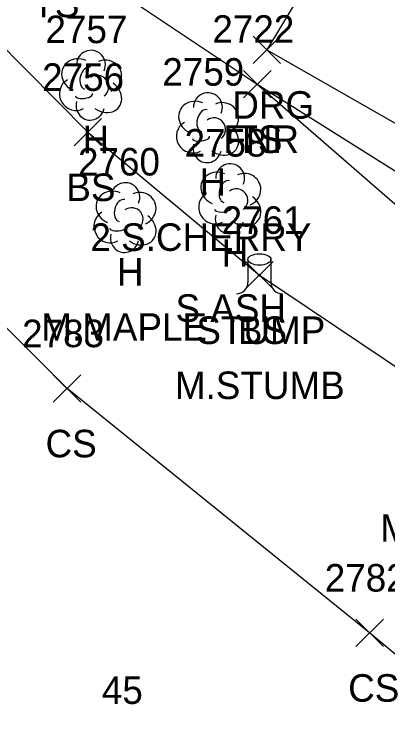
# Model space of a CAD drawing. Extents: x 1499292 to 1501024, y 534584 to 538043.
# Drawn here: x 1499593.1 to 1499620.2, y 537765.7 to 537816.8 of the extents above; entities that cross this region are included whole.
import ezdxf

# ---------------------------------------------------------------- set-up
doc = ezdxf.new("R2010")
doc.units = 0
for name, color, linetype in [('C_I', 7, 'Continuous'), ('L_A', 7, 'Continuous'), ('L_C', 7, 'Continuous'), ('L_I', 7, 'Continuous'), ('L_TIC', 7, 'Continuous'), ('LELB', 7, 'Continuous'), ('LFNC', 7, 'Continuous'), ('LTD', 7, 'Continuous'), ('LTS', 7, 'Continuous'), ('R_A', 7, 'Continuous'), ('R_TIC', 7, 'Continuous'), ('RDG', 7, 'Continuous')]:
    doc.layers.add(name, color=color, linetype=linetype)

msp = doc.modelspace()

# ---------------------------------------------------------------- linework, layer by layer
at = {"layer": 'L_TIC'}
for points in [[(1499609.739, 537810.692), (1499611.739, 537812.692)], [(1499611.739, 537810.692), (1499609.739, 537812.692)], [(1499609.739, 537810.692), (1499611.739, 537812.692)], [(1499611.739, 537810.692), (1499609.739, 537812.692)], [(1499597.435, 537807.198), (1499599.435, 537809.198)], [(1499599.435, 537807.198), (1499597.435, 537809.198)], [(1499609.893, 537796.818), (1499611.893, 537798.818)], [(1499611.893, 537796.818), (1499609.893, 537798.818)], [(1499595.925, 537788.586), (1499597.925, 537790.586)], [(1499597.925, 537788.586), (1499595.925, 537790.586)], [(1499617.899, 537770.836), (1499619.899, 537772.836)], [(1499619.899, 537770.836), (1499617.899, 537772.836)]]:
    msp.add_lwpolyline(points, dxfattribs=at)
at = {"layer": 'LELB'}
for points in [[(1499309.186, 537981.429), (1499342.601, 537967.946), (1499383.002, 537948.454), (1499403.335, 537937.322), (1499425.862, 537923.972), (1499462.056, 537903.885), (1499477.958, 537896.437), (1499498.482, 537885.281), (1499524.089, 537871.298), (1499544.155, 537861.141), (1499587.091, 537836.791), (1499598.177, 537827.35), (1499596, 537821.552), (1499610.739, 537811.692), (1499624.068, 537800.087), (1499630.641, 537795.692), (1499636.949, 537791.6), (1499648.607, 537781.35)], [(1499473.284, 537889.721), (1499498.471, 537879.808), (1499498.645, 537874.964), (1499522.472, 537856.451), (1499547.406, 537847.481), (1499543.068, 537839.362), (1499550.539, 537830.456), (1499554.894, 537825.457), (1499558.691, 537827.698), (1499558.309, 537830.261), (1499565.321, 537832.423), (1499575.95, 537829.995), (1499584.046, 537827.015), (1499587.206, 537819.565), (1499598.435, 537808.198), (1499610.893, 537797.818), (1499632.622, 537783.246), (1499641.436, 537777.369), (1499648.073, 537774.807), (1499656.022, 537768.512), (1499664.288, 537756.487)], [(1499660.39, 537740.632), (1499639.629, 537754.597), (1499618.899, 537771.836), (1499596.925, 537789.586), (1499575.999, 537810.483), (1499560.292, 537815.474)]]:
    msp.add_lwpolyline(points, dxfattribs=at)
at = {"layer": 'LFNC'}
msp.add_lwpolyline([(1499610.739, 537811.692), (1499626.25, 537801.938), (1499645.323, 537790.222), (1499651.803, 537781.891)], dxfattribs=at)
at = {"layer": 'LTD'}
for p, q in [((1499598.619, 537811.668), (1499598.619, 537811.668)), ((1499598.619, 537811.668), (1499598.619, 537811.668)), ((1499607.113, 537808.578), (1499607.113, 537808.578)), ((1499607.113, 537808.578), (1499607.113, 537808.578)), ((1499608.725, 537803.426), (1499608.725, 537803.426)), ((1499608.725, 537803.426), (1499608.725, 537803.426)), ((1499601.118, 537802.053), (1499601.118, 537802.053)), ((1499601.118, 537802.053), (1499601.118, 537802.053))]:
    msp.add_line(p, q, dxfattribs=at)
for centre in [(1499598.666, 537813.102), (1499607.159, 537810.012), (1499608.772, 537804.86), (1499601.164, 537803.487)]:
    msp.add_arc(centre, 1.047, 335.5272, 180.9563, dxfattribs=at)
for centre, major_axis, ratio, start_param, end_param in [((1499597.828, 537812.334), (1.21, -0.512), 0.895232, 1.570796, 4.712389), ((1499599.661, 537812.251), (-1.141, -0.483), 0.949671, 1.570796, 4.712389), ((1499598.411, 537812.126), (-0.208, -0.792), 0.645439, 3.141593, 6.283185), ((1499599.119, 537811.501), (-0.5, 0.667), 0.989748, 3.141593, 6.283185), ((1499597.536, 537810.959), (0.584, -1.042), 0.959034, 3.141593, 6.283185), ((1499599.62, 537810.835), (-1.09, 0.792), 0.841452, 1.570796, 4.712389), ((1499598.161, 537810.918), (-0.625, -0.083), 0.423636, 0, 3.141593), ((1499598.62, 537810.168), (0.265, 1.061), 0.942809, 1.570796, 4.712389), ((1499606.321, 537809.245), (1.21, -0.512), 0.895232, 1.570796, 4.712389), ((1499608.154, 537809.162), (-1.141, -0.483), 0.949671, 1.570796, 4.712389), ((1499606.904, 537809.037), (-0.208, -0.792), 0.645439, 3.141593, 6.283185), ((1499607.613, 537808.412), (-0.5, 0.667), 0.989748, 3.141593, 6.283185), ((1499606.029, 537807.87), (0.584, -1.042), 0.959034, 3.141593, 6.283185), ((1499608.113, 537807.745), (-1.09, 0.792), 0.841452, 1.570796, 4.712389), ((1499606.654, 537807.828), (-0.625, -0.083), 0.423636, 0, 3.141593), ((1499607.113, 537807.078), (0.265, 1.061), 0.942809, 1.570796, 4.712389), ((1499607.933, 537804.093), (1.21, -0.512), 0.895232, 1.570796, 4.712389), ((1499609.767, 537804.01), (-1.141, -0.483), 0.949671, 1.570796, 4.712389), ((1499608.517, 537803.884), (-0.208, -0.792), 0.645439, 3.141593, 6.283185), ((1499600.326, 537802.719), (1.21, -0.512), 0.895232, 1.570796, 4.712389), ((1499609.225, 537803.26), (-0.5, 0.667), 0.989748, 3.141593, 6.283185), ((1499602.159, 537802.636), (-1.141, -0.483), 0.949671, 1.570796, 4.712389), ((1499607.642, 537802.718), (0.584, -1.042), 0.959034, 3.141593, 6.283185), ((1499600.909, 537802.511), (-0.208, -0.792), 0.645439, 3.141593, 6.283185), ((1499609.725, 537802.593), (-1.09, 0.792), 0.841452, 1.570796, 4.712389), ((1499601.618, 537801.886), (-0.5, 0.667), 0.989748, 3.141593, 6.283185), ((1499608.267, 537802.676), (-0.625, -0.083), 0.423636, 0, 3.141593), ((1499600.034, 537801.344), (0.584, -1.042), 0.959034, 3.141593, 6.283185), ((1499602.118, 537801.22), (-1.09, 0.792), 0.841452, 1.570796, 4.712389), ((1499608.725, 537801.926), (0.265, 1.061), 0.942809, 1.570796, 4.712389), ((1499600.659, 537801.303), (-0.625, -0.083), 0.423636, 0, 3.141593), ((1499601.118, 537800.553), (0.265, 1.061), 0.942809, 1.570796, 4.712389)]:
    msp.add_ellipse(centre, major_axis=major_axis, ratio=ratio, start_param=start_param, end_param=end_param, dxfattribs=at)
at = {"layer": 'LTS'}
for p, q in [((1499610.064, 537798.958), (1499610.064, 537797.291)), ((1499611.73, 537798.791), (1499611.73, 537798.958)), ((1499611.73, 537798.958), (1499611.73, 537797.291)), ((1499610.897, 537797.815), (1499610.897, 537797.815)), ((1499610.897, 537797.815), (1499610.897, 537797.815)), ((1499610.897, 537797.791), (1499610.897, 537797.791))]:
    msp.add_line(p, q, dxfattribs=at)
msp.add_circle((1499610.897, 537797.815), 0.0833, dxfattribs=at)
for centre, start, end in [((1499609.23, 537797.291), 270, 360), ((1499612.564, 537797.291), 180, 270)]:
    msp.add_arc(centre, 0.833, start, end, dxfattribs=at)
msp.add_ellipse((1499610.897, 537798.958), major_axis=(-0.833, 0), ratio=0.5, dxfattribs=at)
at = {"layer": 'R_TIC'}
for points in [[(1499610.438, 537813.178), (1499612.438, 537815.178)], [(1499612.438, 537813.178), (1499610.438, 537815.178)]]:
    msp.add_lwpolyline(points, dxfattribs=at)
at = {"layer": 'RDG'}
msp.add_lwpolyline([(1499616.247, 537822.183), (1499611.438, 537814.178), (1499627.998, 537804.719), (1499648.228, 537793.601), (1499657.65, 537787.037), (1499661.233, 537780.563), (1499662.782, 537771.708), (1499664.288, 537756.487), (1499660.39, 537740.632), (1499648.725, 537728.571), (1499635.519, 537714.664), (1499643.061, 537703.46), (1499654.084, 537709.775), (1499666.097, 537716.349), (1499687.017, 537701.096), (1499694.358, 537709.594), (1499686.467, 537716.113), (1499685.219, 537725.482), (1499686.936, 537727.795), (1499688.073, 537727.086)], dxfattribs=at)

# ---------------------------------------------------------------- texts
at = {"layer": 'C_I'}
msp.add_text('45', height=2, dxfattribs=at).set_placement((1499599.455, 537766.674))
at = {"layer": 'L_A'}
for s, p in [('TS', (1499594.409, 537816.552)), ('FNR', (1499608.275, 537806.692)), ('TS', (1499609.149, 537806.692)), ('H', (1499598.052, 537806.668)), ('BS', (1499596.876, 537803.198)), ('H', (1499606.546, 537803.578)), ('H', (1499608.158, 537798.426)), ('H', (1499600.551, 537797.053)), ('STUMP', (1499606.318, 537792.818)), ('BS', (1499609.333, 537792.818)), ('CS', (1499595.366, 537784.586)), ('CS', (1499617.34, 537766.836))]:
    msp.add_text(s, height=2, dxfattribs=at).set_placement(p)
at = {"layer": 'L_C'}
for s, p in [('2 S.CHERRY', (1499598.624, 537799.578)), ('S.ASH', (1499604.804, 537794.426)), ('M.MAPLE', (1499595.055, 537793.053)), ('M.STUMB', (1499604.759, 537788.818)), ('M.ASH', (1499619.679, 537778.458))]:
    msp.add_text(s, height=2, dxfattribs=at).set_placement(p)
at = {"layer": 'L_I'}
for s, p in [('2757', (1499595.36, 537814.668)), ('2722', (1499607.48, 537814.692)), ('2722', (1499607.48, 537814.692)), ('2759', (1499603.845, 537811.578)), ('2756', (1499595.12, 537811.198)), ('2758', (1499605.465, 537806.426)), ('2760', (1499597.724, 537805.053)), ('2761', (1499608.152, 537800.818)), ('2761', (1499608.152, 537800.818)), ('2783', (1499593.665, 537792.586)), ('2782', (1499615.64, 537774.836))]:
    msp.add_text(s, height=2, dxfattribs=at).set_placement(p)
at = {"layer": 'R_A'}
msp.add_text('DRG', height=2, dxfattribs=at).set_placement((1499608.926, 537809.178))

doc.saveas('drawing.dxf')
